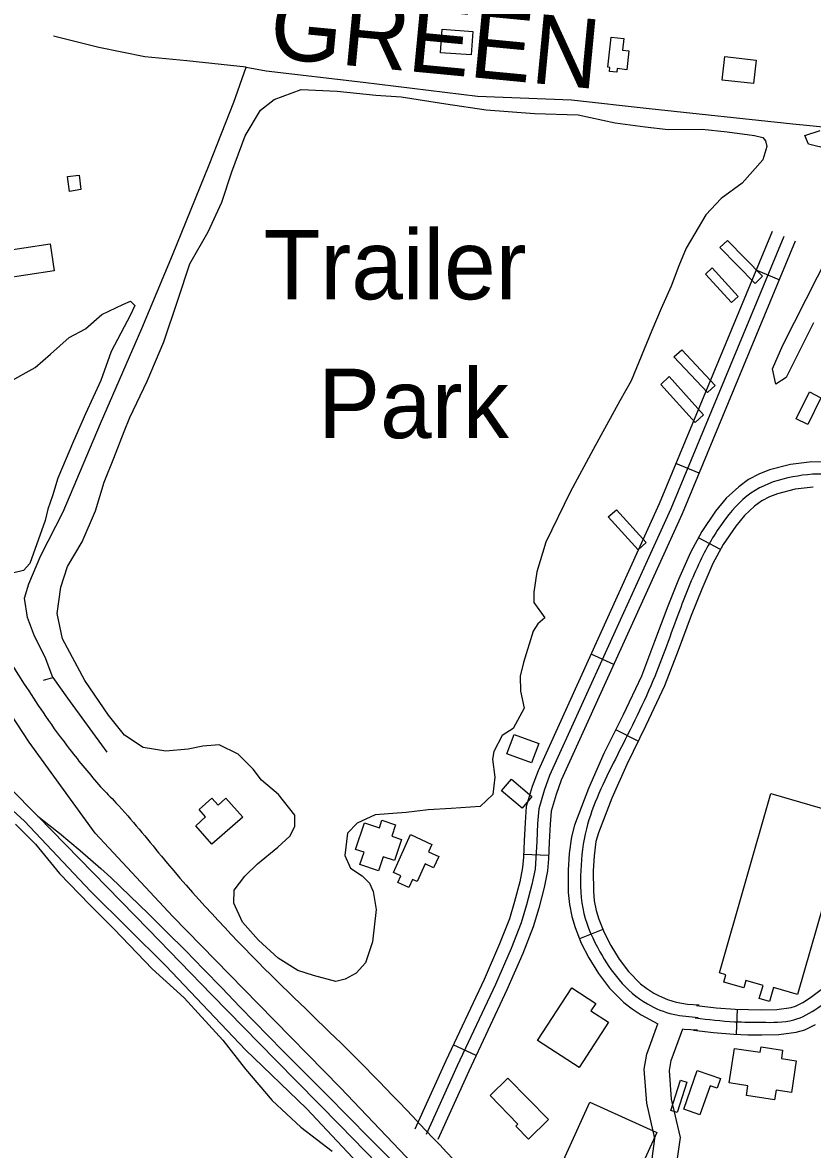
# Model space of a CAD drawing. Extents: x 3715084 to 3753216, y 488173 to 513963.
# Drawn here: x 3736776 to 3737721, y 501137 to 502484 of the extents above; entities that cross this region are included whole.
import ezdxf

# ---------------------------------------------------------------- set-up
doc = ezdxf.new("R2010")
doc.units = 0
for name, color, linetype in [('V-BLDG-IDEN', 7, 'Continuous'), ('V-BLDG-OTLN', 7, 'Continuous'), ('V-RAIL-TRAK', 7, 'Continuous'), ('V-RIVR-IDEN', 7, 'Continuous'), ('V-ROAD-CNTR', 7, 'Continuous'), ('V-SITE-VEGE', 7, 'Continuous'), ('V-TOPO-SHOR', 7, 'Continuous')]:
    doc.layers.add(name, color=color, linetype=linetype)

msp = doc.modelspace()

# ---------------------------------------------------------------- linework, layer by layer
at = {"layer": 'V-BLDG-OTLN'}
for points in [[(3737277.7, 502476.5), (3737314.4, 502473.9), (3737312.5, 502445.7), (3737275.8, 502448.3)], [(3737475.9, 502431.2), (3737479.8, 502467), (3737495.1, 502465.3), (3737493.5, 502451.5), (3737501.3, 502450.7), (3737498.8, 502428.1), (3737487, 502429.4), (3737486.6, 502425.2), (3737477.9, 502426.1), (3737478.4, 502430.9)], [(3737650.3, 502411.5), (3737612.7, 502415.7), (3737615.8, 502443.7), (3737653.4, 502439.5)], [(3736832.1, 502282.3), (3736829.8, 502300.3), (3736843.6, 502302.1), (3736845.8, 502285)], [(3736745.9, 502210.5), (3736809, 502220.1), (3736814, 502187.6), (3736750.9, 502178)], [(3737619.1, 502223.9), (3737661.1, 502181.1), (3737652.3, 502172.4), (3737609.9, 502215.7)], [(3737600.7, 502191.2), (3737631.8, 502156.9), (3737623.8, 502149.6), (3737592.9, 502183.8)], [(3737564.6, 502093), (3737604.3, 502050.6), (3737595.2, 502042.1), (3737555.1, 502085)], [(3737549.2, 502061.3), (3737590.4, 502015.6), (3737580.4, 502006.5), (3737539.4, 502051.8)], [(3737730.8, 502036), (3737715, 502004), (3737701.3, 502010.7), (3737717.1, 502042.8)], [(3737486.3, 501902), (3737522, 501862.8), (3737512.2, 501853.9), (3737476.4, 501893.4)], [(3737363.8, 501633.3), (3737393.4, 501622.4), (3737384.9, 501599.3), (3737355.3, 501610.2)], [(3737360.6, 501579.9), (3737385, 501559.3), (3737373.4, 501545.4), (3737348.9, 501566.1)], [(3737609.4, 501348.3), (3737671.1, 501562.6), (3737764.2, 501535.8), (3737702.8, 501322.5), (3737674.2, 501330.7), (3737669.4, 501314.2), (3737657.1, 501317.7), (3737661.6, 501333.2), (3737641.2, 501339.1), (3737638.8, 501330.4), (3737614.7, 501337.3), (3737617.3, 501346.1)], [(3737039.3, 501534.3), (3737002.5, 501502.1), (3736983.1, 501524.3), (3736994.9, 501534.7), (3736987.2, 501543.6), (3737002.6, 501557), (3737009.8, 501548.7), (3737019.3, 501557)], [(3737229.2, 501507.8), (3737220.8, 501482.7), (3737207.5, 501487.2), (3737201.9, 501470.3), (3737179.6, 501477.7), (3737184.5, 501492.5), (3737174.4, 501495.8), (3737185.1, 501527.9), (3737203, 501521.9), (3737205.9, 501530.8), (3737222.1, 501525.4), (3737217.5, 501511.7)], [(3737219.5, 501468.5), (3737240.1, 501513.6), (3737265.7, 501501.9), (3737261.7, 501493.1), (3737274, 501487.5), (3737267.7, 501473.8), (3737257.5, 501478.5), (3737247.9, 501457.5), (3737242.5, 501460), (3737238.1, 501450.3), (3737224.8, 501456.3), (3737228.5, 501464.4)], [(3737441.6, 501235.4), (3737392, 501267.6), (3737432.8, 501330.4), (3737461.5, 501311.8), (3737455.8, 501303), (3737476.7, 501289.4)], [(3737627.5, 501258.1), (3737658.2, 501253.4), (3737659.2, 501259.9), (3737685, 501255.9), (3737683.5, 501245.9), (3737701.4, 501243.2), (3737695.5, 501205.4), (3737677.3, 501208.2), (3737675.5, 501196.6), (3737641.7, 501201.8), (3737643.5, 501213.2), (3737621.1, 501216.7)], [(3737356.6, 501222.5), (3737404.9, 501172.9), (3737381, 501149.7), (3737366.1, 501165.1), (3737368.4, 501167.4), (3737335.1, 501201.6)], [(3737566.8, 501185.3), (3737582.7, 501231.8), (3737610.6, 501222.2), (3737606.6, 501210.5), (3737598.2, 501213.4), (3737586.2, 501178.6)], [(3737570.4, 501217.6), (3737558.8, 501181.4), (3737551.3, 501183.8), (3737562.9, 501220)], [(3737534.4, 501157.5), (3737485.2, 501049.3), (3737405.5, 501085.6), (3737454.6, 501193.8)]]:
    msp.add_lwpolyline(points, close=True, dxfattribs=at)
at = {"layer": 'V-RAIL-TRAK'}
for points in [[(3736691.5, 501639.2), (3736794.5, 501535.5), (3736926.6, 501400.2), (3737002.6, 501322), (3737078.8, 501244), (3737155.3, 501166.3), (3737215.7, 501104.5), (3737275.9, 501042.6), (3737336, 500980.6), (3737396, 500918.4), (3737413.9, 500901), (3737431.8, 500883.4), (3737449.5, 500865.7)], [(3736794.5, 501535.5), (3736807.4, 501525.5), (3736820.1, 501515.3), (3736832.7, 501505), (3736845.1, 501494.5), (3736857.4, 501483.9), (3736869.6, 501473.1), (3736881.7, 501462.2), (3736904.2, 501440.6), (3736926.6, 501418.9), (3736948.7, 501397), (3736970.8, 501375), (3736992.6, 501352.8), (3737014.3, 501330.4), (3737035.9, 501307.9), (3737087.5, 501255.3), (3737139.4, 501202.8), (3737191.3, 501150.5), (3737224.6, 501117.4)]]:
    msp.add_lwpolyline(points, dxfattribs=at)
at = {"layer": 'V-ROAD-CNTR'}
for p, q in [((3737681, 502176.8), (3737653.2, 502188.3)), ((3737585.2, 501945.9), (3737557.5, 501957.4)), ((3737610.7, 501854.4), (3737584.3, 501868.6)), ((3737483.2, 501717.1), (3737455.9, 501729.5)), ((3737512.3, 501625.4), (3737485.4, 501638.7)), ((3737405.2, 501488.6), (3737375.2, 501489.8)), ((3737470, 501400.3), (3737442.2, 501389)), ((3737630.7, 501304.8), (3737629.6, 501274.9)), ((3737318.4, 501249.4), (3737291.2, 501262.2))]:
    msp.add_line(p, q, dxfattribs=at)
for points in [[(3737672.4, 502234.5), (3737537.4, 501909.1), (3737392.5, 501590), (3737385.7, 501571.1), (3737378.5, 501547.2), (3737377.1, 501528), (3737375.9, 501506), (3737375.1, 501486.6), (3737374.1, 501474.3), (3737370.7, 501457.3), (3737364.4, 501433.7), (3737358.2, 501412.9), (3737346.6, 501383), (3737328.1, 501340.5), (3737282.3, 501243.3), (3737245.2, 501161.4)], [(3737686.3, 502228.8), (3737551.2, 501903.1), (3737406.4, 501584.3), (3737399.9, 501566.3), (3737393.3, 501544.5), (3737392, 501527.1), (3737390.9, 501505.2), (3737390, 501485.7), (3737389, 501472.2), (3737385.3, 501453.9), (3737378.8, 501429.7), (3737372.4, 501408.1), (3737360.5, 501377.3), (3737341.7, 501334.3), (3737295.9, 501237), (3737258.9, 501155.2)], [(3737700.1, 502223), (3737564.9, 501897.1), (3737420.3, 501578.6), (3737414.2, 501561.6), (3737408.1, 501541.7), (3737407, 501526.1), (3737405.8, 501504.5), (3737405, 501484.8), (3737403.8, 501470.2), (3737399.9, 501450.5), (3737393.3, 501425.6), (3737386.7, 501403.2), (3737374.3, 501371.6), (3737355.4, 501328.1), (3737309.6, 501230.7), (3737272.6, 501149)], [(3737745.6, 501958.9), (3737719.9, 501959.3), (3737694.5, 501956.1), (3737669.5, 501949.8), (3737656.7, 501944.7), (3737644.3, 501938), (3737632.5, 501929.6), (3737617.5, 501915.9), (3737604.8, 501900.3), (3737588.4, 501876.2), (3737574.7, 501850.8), (3737560.7, 501818.6), (3737547.7, 501786.6), (3737532, 501744.4), (3737516.1, 501703.2), (3737494.4, 501657), (3737471.4, 501610.4), (3737452.9, 501568.7), (3737436.2, 501525.1), (3737432.4, 501511.1), (3737429.6, 501490.9), (3737428.6, 501471.2), (3737428.7, 501444.4), (3737430.1, 501430.1), (3737432.8, 501415.9), (3737436.8, 501402.5), (3737444.3, 501384), (3737453.4, 501366.2), (3737464.7, 501347.7), (3737478.1, 501330), (3737495.2, 501312.9), (3737505.2, 501305.2), (3737515.7, 501298.3), (3737535.8, 501287.4)], [(3737721.5, 501929.2), (3737700, 501926.6), (3737678.8, 501921.2), (3737669.5, 501917.5), (3737660.2, 501912.5), (3737651.4, 501906.2), (3737639.4, 501895.2), (3737628.9, 501882.3), (3737614, 501860.6), (3737601.7, 501837.6), (3737588.4, 501807), (3737575.6, 501775.7), (3737560, 501733.8), (3737543.8, 501691.4), (3737521.5, 501644), (3737498.6, 501597.6), (3737480.6, 501557.2), (3737464.7, 501515.8), (3737461.8, 501505.2), (3737459.5, 501488.1), (3737458.6, 501470.5), (3737458.7, 501445.9), (3737459.8, 501434.5), (3737462, 501423), (3737465.1, 501412.4), (3737471.6, 501396.5), (3737479.6, 501380.9), (3737489.5, 501364.6), (3737500.8, 501349.8), (3737515.1, 501335.4), (3737522.6, 501329.6), (3737531, 501324.1), (3737537.2, 501320.8), (3737547.3, 501316.6), (3737557.9, 501313.5), (3737571.1, 501310.9), (3737585.1, 501310.1)], [(3737582.1, 501309.5), (3737605.4, 501306.7), (3737628.4, 501304.9), (3737644.1, 501304.4), (3737659.9, 501304.3), (3737678.1, 501304.7), (3737695.3, 501306.9), (3737700.5, 501308.4), (3737709.3, 501312.8), (3737718.4, 501318.8), (3737737.3, 501333.1)], [(3737424.2, 500987), (3737479.2, 501049.3), (3737508.3, 501075.6), (3737526.9, 501110.8), (3737532.4, 501150.3), (3737522.5, 501192.7), (3737519.4, 501233.3), (3737522.7, 501251.3), (3737535.8, 501287.4)], [(3737555.4, 501098.4), (3737562.9, 501151.7), (3737552.2, 501197.2), (3737549.6, 501231.7), (3737551.8, 501243.4), (3737565.6, 501281.5)], [(3737565.6, 501281.5), (3737567.4, 501281.1), (3737583.2, 501280.1)], [(3737578.6, 501279.7), (3737602.5, 501276.9), (3737626.7, 501275), (3737643.5, 501274.4), (3737660.2, 501274.3), (3737680.3, 501274.8), (3737701.4, 501277.4), (3737711.6, 501280.4), (3737724.3, 501286.8)]]:
    msp.add_lwpolyline(points, dxfattribs=at)
for points in [[(3736554.4, 502400), (3736562.9, 502324.3), (3736569.3, 502271.5), (3736576.3, 502228.7), (3736585.8, 502169.2), (3736596.2, 502125.5), (3736607, 502079.2), (3736619.6, 502038.8), (3736635.8, 501981.2), (3736653.9, 501939.2), (3736675.4, 501881.2), (3736693.2, 501841.7), (3736715.5, 501806.1), (3736735.3, 501769.5), (3736754.8, 501731.7), (3736780.6, 501689.7), (3736803.6, 501655.2), (3736832.2, 501615.9), (3736869.3, 501570.8)], [(3737580.4, 501294.6), (3737627.6, 501289.9), (3737660.1, 501289.3), (3737698.3, 501292.1), (3737727.1, 501306.5), (3737765.2, 501339), (3737785.7, 501370.1), (3737797.8, 501450.3), (3737812.6, 501559.8), (3737831.8, 501727.4), (3737839.5, 501813.1), (3737833.9, 501881.9), (3737817.3, 501911.4), (3737780.7, 501934.6), (3737744.1, 501943.9), (3737697.2, 501941.3), (3737652.3, 501925.2), (3737616.8, 501891.3), (3737588.2, 501844.2), (3737561.6, 501781.2), (3737529.9, 501697.3), (3737485, 501604), (3737450.4, 501520.4), (3737443.6, 501470.9), (3737447.4, 501419.5), (3737466.5, 501373.5), (3737489.5, 501339.9), (3737523.3, 501311.2), (3737554.3, 501298.9), (3737584.2, 501295.1)], [(3736869.3, 501570.8), (3736887.8, 501551.8), (3736942.1, 501487.9), (3737065.6, 501353.3), (3737177.9, 501243.5), (3737307, 501108.7), (3737445.3, 500966.9), (3737592.7, 500816.7), (3737676, 500733.7), (3737740.6, 500677.8), (3737805.8, 500628.8), (3737892.7, 500568.7), (3738017.6, 500503.3), (3738130.9, 500451.3), (3738238.1, 500416), (3738348.4, 500388), (3738440.5, 500371.6), (3738557.7, 500359.5), (3738683.6, 500360.5), (3738888.2, 500363.1), (3739333.1, 500377.3), (3739664.7, 500391.6), (3739914, 500401.2), (3740094.4, 500408.9), (3740242.1, 500410.9), (3740383, 500409.7), (3740562.1, 500406.8), (3740764.5, 500396.7), (3740922.6, 500388.4), (3741040, 500381.5), (3741282.5, 500371.6), (3741550.9, 500357.4), (3741866.1, 500340.2), (3742063.1, 500339.1), (3742198.4, 500332.9), (3742359.8, 500340.7), (3742549.7, 500351.3), (3742757.5, 500365.7), (3742837.1, 500371.5)]]:
    msp.add_spline(points, degree=3, dxfattribs=at)
at = {"layer": 'V-SITE-VEGE'}
for points in [[(3737060.6, 502379.9), (3737076.8, 502392.5), (3737109.3, 502404.5), (3737152.3, 502402.4), (3737198.4, 502397.6), (3737228.8, 502395.5), (3737282.3, 502387.1), (3737330.5, 502380.3), (3737388.2, 502375.6), (3737440.6, 502374), (3737484.7, 502364.5), (3737520.8, 502359.8)], [(3737520.8, 502359.8), (3737548.1, 502356.6), (3737589, 502357.1), (3737618.9, 502354), (3737651.4, 502349.3), (3737661.3, 502347.2), (3737664.5, 502343), (3737666, 502336.1), (3737661.3, 502320.4), (3737636.7, 502292.6), (3737611.5, 502274.3), (3737593.1, 502254.4), (3737580, 502232.4), (3737569.5, 502214.6), (3737561.1, 502193.6), (3737551.7, 502169.5), (3737539.6, 502142.7), (3737528.6, 502116.5), (3737504, 502056.3), (3737490.3, 502032.1), (3737458.3, 501974), (3737431, 501923.1), (3737401.7, 501863.4), (3737391.2, 501827.7), (3737387.5, 501803.6), (3737387.5, 501791), (3737400.6, 501772.7), (3737392.3, 501765.5), (3737386.6, 501756.9), (3737375.2, 501719.2), (3737371.2, 501703), (3737371.7, 501685.1), (3737375.9, 501664.7), (3737362.8, 501640.6), (3737349.7, 501632.2), (3737339.7, 501612.8), (3737338.1, 501603.9), (3737340.7, 501582.4), (3737338.6, 501561.4), (3737323.4, 501547.3), (3737288.8, 501544.7), (3737261, 501543.1), (3737234.8, 501540), (3737197.6, 501537.4), (3737176.1, 501527.4), (3737164.6, 501515.4), (3737161.4, 501488.6), (3737168.2, 501473.4), (3737182.4, 501464.5), (3737190.8, 501455.6), (3737195.5, 501445.6), (3737199.1, 501424.1), (3737194.4, 501385.3), (3737186, 501360.2), (3737175, 501348.1), (3737161.9, 501340.8), (3737150.9, 501338.2), (3737124.1, 501345), (3737105.3, 501351.3), (3737081.7, 501366), (3737058.1, 501387.5), (3737039.2, 501409), (3737028.8, 501431.5), (3737029.3, 501447.3), (3737041.9, 501464), (3737057.1, 501478.7), (3737081.2, 501498.6), (3737095.9, 501511.7), (3737101.7, 501523.2), (3737101.7, 501536.9), (3737082.3, 501561.5), (3737061.8, 501578.8), (3737051.9, 501591.9), (3737034.1, 501609.8), (3737011, 501620.8), (3736991.6, 501619.2), (3736974.3, 501615.6), (3736947.6, 501613.5), (3736920.3, 501617.7), (3736897.8, 501632.4), (3736878.9, 501656.5), (3736850.6, 501697.9), (3736823.9, 501747.7), (3736817.6, 501778.1), (3736821.8, 501809.6), (3736829.7, 501834.2), (3736847.5, 501863.6), (3736863.3, 501900.8), (3736873.8, 501934.9), (3736885.3, 501963.7), (3736897.4, 501995.7), (3736904.2, 502012.4), (3736925.2, 502055.9), (3736945.1, 502102.6), (3736961.9, 502152.4), (3736976.1, 502195.9), (3736998.1, 502234.2), (3737014.4, 502269.8), (3737026.5, 502306), (3737042.2, 502349), (3737060.6, 502379.9)], [(3737740.2, 502333.1), (3737715.8, 502339.2), (3737711.7, 502349.4), (3737730, 502355.5)], [(3737721.9, 502125.3), (3737689.3, 502060.1), (3737677.1, 502052), (3737673, 502070.3), (3737685.2, 502098.8), (3737754.5, 502235.3)], [(3736759.5, 502054.4), (3736791, 502072.2), (3736809.3, 502088), (3736831.9, 502107.9), (3736851.3, 502118.4), (3736870.7, 502135.6), (3736895.9, 502147.2), (3736905.3, 502151.4), (3736910.5, 502146.1), (3736905.3, 502135.1), (3736882.2, 502091.1), (3736869.6, 502056.5), (3736851.2, 502016.7), (3736837.1, 501984.2), (3736818.2, 501939.6), (3736811.9, 501918.6), (3736806.1, 501902.9), (3736803, 501889.3), (3736784.6, 501837.9), (3736777.3, 501829.5), (3736765.7, 501826.4)], [(3736767.5, 501526.1), (3736791.5, 501502.1), (3736820.3, 501467), (3736856, 501429.9), (3736885.6, 501400.4), (3736930.9, 501353), (3736969.4, 501318.6), (3737015.4, 501267.7), (3737042.8, 501233.4), (3737074.4, 501195.6), (3737108.8, 501164), (3737146.5, 501135.1)]]:
    msp.add_lwpolyline(points, dxfattribs=at)
at = {"layer": 'V-TOPO-SHOR'}
for points in [[(3737043.3, 502431.1), (3736972.5, 502438.7), (3736922.4, 502443.5), (3736867.4, 502454.5), (3736813.1, 502468.3)], [(3736812.2, 501701.6), (3736803.2, 501725.6), (3736790.2, 501751), (3736782, 501773), (3736778.5, 501796.4), (3736783.4, 501813.6), (3736797.8, 501847.2), (3736824.6, 501899.4), (3736869.3, 502005.2), (3736918.8, 502118.5), (3736955.2, 502206.5), (3736999.3, 502314.3), (3737028.8, 502389.2), (3737043.3, 502431.1), (3737067.3, 502426.9), (3737183.4, 502413.2), (3737320.1, 502396.6), (3737432.7, 502392.1)], [(3737432.7, 502392.1), (3737525.5, 502381.6), (3737697.1, 502363.2), (3737900.2, 502343.3), (3738014.7, 502333.1), (3738248, 502308.1), (3738278.3, 502304.9), (3738387.9, 502293), (3738469.4, 502280.9)], [(3736801.2, 501698.1), (3736812.2, 501701.6), (3736830, 501676.8), (3736876.7, 501612.2)], [(3737438.6, 500922.8), (3737415.8, 500947), (3737323, 501039.1), (3737258.5, 501103.7), (3737156.2, 501210.9), (3737058, 501311.3), (3736955.6, 501415.7), (3736862.9, 501515.4), (3736784, 501624), (3736755.1, 501667.9), (3736764.1, 501675.5)], [(3736698.1, 501614.4), (3736704.3, 501602.7), (3736722.8, 501580), (3736778.4, 501529.8), (3736857.4, 501446), (3736947.4, 501356.7), (3737042.8, 501256.3), (3737115.6, 501186.2), (3737201.5, 501094.8), (3737284.6, 501006.9), (3737367, 500925.1), (3737434.3, 500852.2), (3737506.4, 500781.4)]]:
    msp.add_lwpolyline(points, dxfattribs=at)

# ---------------------------------------------------------------- texts
at = {"layer": 'V-BLDG-IDEN'}
for s, p in [('Trailer', (3737064.4, 502153.6)), ('Park', (3737129.6, 501987.6))]:
    msp.add_text(s, height=83, dxfattribs=at).set_placement(p)
at = {"layer": 'V-RIVR-IDEN'}
msp.add_text('GREEN', height=83, rotation=354.5317, dxfattribs=at).set_placement((3737069.3, 502442.5))

doc.saveas('drawing.dxf')
